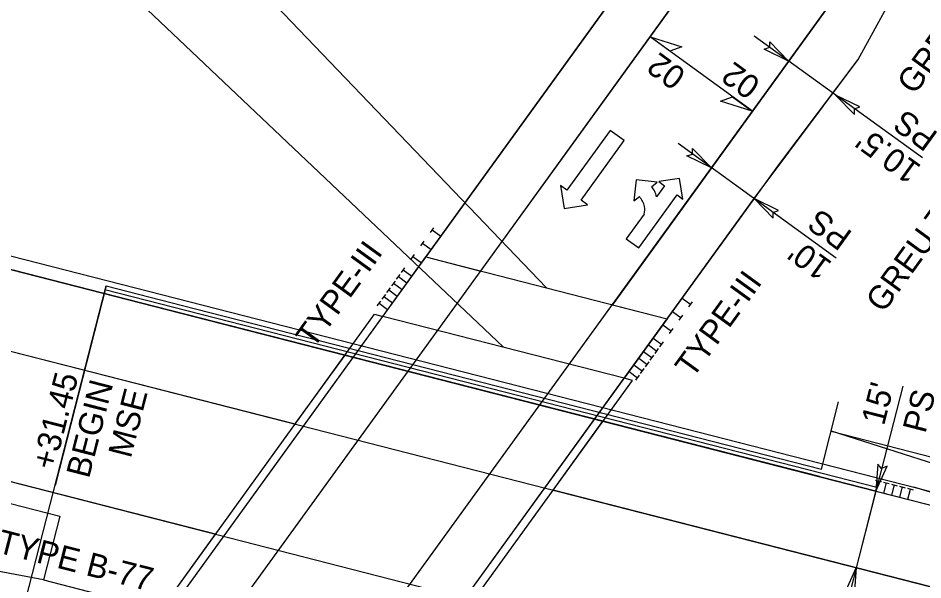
# Model space of a CAD drawing. Extents: x 1183930 to 1185370, y 573068 to 574871.
# Drawn here: x 1184495.2 to 1184666.9, y 574087.2 to 574193.8 of the extents above; entities that cross this region are included whole.
import ezdxf

# ---------------------------------------------------------------- set-up
doc = ezdxf.new("R2010")
doc.units = 0
for name, color, linetype in [('Default', 7, 'Continuous'), ('E_NCDOT_Terrain_Model_Flow_Arrows', 7, 'Continuous'), ('E_NCDOT_Terrain_Model_Spot_Elevation', 7, 'Continuous'), ('E_NCDOT_Vertical_Profile_Ground_Line', 7, 'Continuous'), ('P_NCDOT_Horizontal_Alignment', 7, 'Continuous'), ('P_NCDOT_Horizontal_Alignment_Curve_and_Spiral_Data', 7, 'Continuous'), ('P_NCDOT_Horizontal_Alignment_Direction_Label', 7, 'Continuous'), ('P_NCDOT_Horizontal_Alignment_Station_Label', 7, 'Continuous'), ('P_NCDOT_Horizontal_Alignment_Tick_Large', 7, 'Continuous'), ('P_NCDOT_Horizontal_Alignment_Tick_Small', 7, 'Continuous'), ('P_NCDOT_Vertical_Profile_Grade', 7, 'Continuous'), ('P_SMU_Deck', 7, 'Continuous'), ('PC_BEAM', 7, 'Continuous'), ('PC_COLUMN', 7, 'Continuous'), ('PC_OBJECT', 7, 'Continuous'), ('PC_PADFOOTING', 7, 'Continuous'), ('PC_SLAB', 7, 'Continuous'), ('PS_HATCH', 7, 'Continuous')]:
    doc.layers.add(name, color=color, linetype=linetype)

msp = doc.modelspace()

# ---------------------------------------------------------------- linework, layer by layer
for points in [[(1184637.83, 574189.33), (1184641.42, 574185.65), (1184636.77, 574187.91), (1184637.82, 574188.26)], [(1184654.95, 574176.94), (1184650.33, 574179.2), (1184653.93, 574175.49), (1184653.93, 574176.6)], [(1184623.18, 574169.08), (1184626.77, 574165.41), (1184622.12, 574167.66), (1184623.17, 574168.01)], [(1184639.48, 574157.28), (1184634.87, 574159.55), (1184638.47, 574155.83), (1184638.47, 574156.94)], [(1184658.38, 574109.19), (1184657.97, 574104.07), (1184660.1, 574108.78), (1184659.07, 574108.38)], [(1184652.15, 574084.85), (1184654.25, 574089.54), (1184653.86, 574084.38), (1184653.15, 574085.23)]]:
    msp.add_lwpolyline(points, close=True)
at = {"layer": 'Default'}
for p, q in [((1184433.21, 574164.19), (1184675.4, 574102.19)), ((1184526.4, 574139.3), (1184647.65, 574108.26))]:
    msp.add_line(p, q, dxfattribs=at)
at = {"layer": 'E_NCDOT_Terrain_Model_Flow_Arrows'}
msp.add_line((1184511.87, 574143.02), (1184526.4, 574139.3), dxfattribs=at)
at = {"layer": 'E_NCDOT_Terrain_Model_Spot_Elevation'}
msp.add_line((1184511.65, 574142.3), (1184658.16, 574104.8), dxfattribs=at)
at = {"layer": 'E_NCDOT_Vertical_Profile_Ground_Line'}
for p, q in [((1184449.47, 573978.44), (1184665.23, 574276.54)), ((1184449.47, 573978.44), (1184665.23, 574276.54)), ((1184654.62, 574185.97), (1184679.82, 574231.89)), ((1184654.62, 574185.97), (1184679.82, 574231.89)), ((1184136.14, 574193.27), (1184503.1, 574099.33)), ((1184136.14, 574193.27), (1184503.1, 574099.33)), ((1184136.14, 574193.27), (1184503.1, 574099.33)), ((1184639.53, 574165.99), (1184654.62, 574185.97)), ((1184639.53, 574165.99), (1184654.62, 574185.97)), ((1184413.69, 573853.97), (1184639.53, 574165.99)), ((1184413.69, 573853.97), (1184639.53, 574165.99)), ((1184487.27, 574147.77), (1184526.03, 574137.85)), ((1184515.9, 574140.44), (1184669.44, 574101.14)), ((1184526.03, 574137.85), (1184657.97, 574104.07)), ((1184503.1, 574099.33), (1184500, 574087.22)), ((1184503.1, 574099.33), (1184500, 574087.22)), ((1184500, 574087.22), (1184592.76, 574063.47)), ((1184500, 574087.22), (1184592.76, 574063.47))]:
    msp.add_line(p, q, dxfattribs=at)
at = {"layer": 'P_NCDOT_Horizontal_Alignment'}
for p, q in [((1184397.22, 573889.19), (1184673.34, 574270.68)), ((1184405.59, 573859.83), (1184695.92, 574260.95)), ((1184143.08, 574220.4), (1184971.37, 574008.35)), ((1184143.08, 574220.4), (1184977.73, 574006.73)), ((1184137.13, 574197.15), (1184965.42, 573985.1)), ((1184137.13, 574197.15), (1184971.78, 573983.48)), ((1184647.65, 574108.26), (1184650.88, 574121)), ((1184649.47, 574115.43), (1184671.64, 574109.76)), ((1184649.48, 574115.48), (1185048.75, 573988.56)), ((1184647.89, 574109.23), (1185053.08, 574005.5)), ((1185048.75, 573988.56), (1184665.2, 574104.8))]:
    msp.add_line(p, q, dxfattribs=at)
at = {"layer": 'P_NCDOT_Horizontal_Alignment_Curve_and_Spiral_Data'}
for p, q in [((1184515.9, 574140.44), (1184511.49, 574141.57)), ((1184657.97, 574104.07), (1184515.9, 574140.44)), ((1184647.27, 574106.81), (1184526.03, 574137.85))]:
    msp.add_line(p, q, dxfattribs=at)
at = {"layer": 'P_NCDOT_Horizontal_Alignment_Direction_Label'}
for p, q in [((1184477.22, 574019.34), (1184562.83, 574137.61)), ((1184478.79, 574018.94), (1184564.39, 574137.21)), ((1184562.83, 574137.61), (1184564.39, 574137.21)), ((1184524.61, 574007.21), (1184610.21, 574125.48)), ((1184526.17, 574006.81), (1184611.78, 574125.08)), ((1184611.78, 574125.08), (1184610.21, 574125.48))]:
    msp.add_line(p, q, dxfattribs=at)
at = {"layer": 'P_NCDOT_Horizontal_Alignment_Station_Label'}
for p, q in [((1184564.39, 574137.21), (1184572.62, 574148.59)), ((1184564.39, 574137.21), (1184572.55, 574148.49)), ((1184610.21, 574125.48), (1184564.39, 574137.21)), ((1184610.21, 574125.48), (1184618.52, 574136.95)), ((1184610.21, 574125.48), (1184618.38, 574136.76))]:
    msp.add_line(p, q, dxfattribs=at)
msp.add_lwpolyline([(1184610.21, 574125.48), (1184564.39, 574137.21), (1184572.55, 574148.49), (1184618.38, 574136.76)], close=True, dxfattribs=at)
at = {"layer": 'P_NCDOT_Horizontal_Alignment_Tick_Large'}
for p, q in [((1184575.38, 574152.4), (1184665.23, 574276.54)), ((1184621.21, 574140.67), (1184639.53, 574165.99)), ((1184500, 574087.22), (1184466.75, 574093.41))]:
    msp.add_line(p, q, dxfattribs=at)
at = {"layer": 'P_NCDOT_Horizontal_Alignment_Tick_Small'}
msp.add_line((1184639.53, 574165.99), (1184654.62, 574185.93), dxfattribs=at)
at = {"layer": 'P_NCDOT_Vertical_Profile_Grade'}
for p, q in [((1184573.43, 574153.11), (1184574.1, 574154.04)), ((1184575.38, 574152.4), (1184573.76, 574153.58)), ((1184564.39, 574137.21), (1184575.38, 574152.4)), ((1184571.6, 574150.58), (1184572.27, 574151.51)), ((1184573.55, 574149.87), (1184571.93, 574151.04)), ((1184569.76, 574148.05), (1184570.43, 574148.98)), ((1184571.72, 574147.34), (1184570.1, 574148.51)), ((1184567.93, 574145.52), (1184568.6, 574146.44)), ((1184569.89, 574144.81), (1184568.27, 574145.98)), ((1184566.1, 574142.99), (1184566.77, 574143.91)), ((1184567.01, 574144.25), (1184567.69, 574145.18)), ((1184568.97, 574143.54), (1184567.35, 574144.72)), ((1184565.18, 574141.72), (1184565.85, 574142.65)), ((1184567.14, 574141.01), (1184565.52, 574142.18)), ((1184568.05, 574142.28), (1184566.43, 574143.45)), ((1184564.27, 574140.45), (1184564.94, 574141.38)), ((1184566.22, 574139.75), (1184564.6, 574140.92)), ((1184610.21, 574125.48), (1184621.21, 574140.67)), ((1184621.21, 574140.67), (1184622.83, 574139.5)), ((1184563.35, 574139.19), (1184564.02, 574140.12)), ((1184565.31, 574138.48), (1184563.69, 574139.65)), ((1184622.49, 574139.03), (1184623.16, 574139.96)), ((1184619.38, 574138.14), (1184621, 574136.97)), ((1184620.66, 574136.5), (1184621.33, 574137.43)), ((1184617.54, 574135.61), (1184619.16, 574134.44)), ((1184618.83, 574133.97), (1184619.5, 574134.9)), ((1184615.71, 574133.08), (1184617.33, 574131.9)), ((1184617, 574131.44), (1184617.67, 574132.37)), ((1184613.88, 574130.55), (1184615.5, 574129.37)), ((1184614.8, 574131.81), (1184616.42, 574130.64)), ((1184616.08, 574130.17), (1184616.75, 574131.1)), ((1184612.96, 574129.28), (1184614.58, 574128.11)), ((1184614.25, 574127.64), (1184614.92, 574128.57)), ((1184615.16, 574128.91), (1184615.84, 574129.84)), ((1184611.13, 574126.75), (1184612.75, 574125.58)), ((1184612.05, 574128.01), (1184613.67, 574126.84)), ((1184613.33, 574126.38), (1184614, 574127.31)), ((1184612.42, 574125.11), (1184613.09, 574126.04)), ((1184657.91, 574106.15), (1184659.02, 574105.87)), ((1184657.97, 574104.07), (1184658.47, 574106.01)), ((1184659.42, 574105.76), (1184660.53, 574105.48)), ((1184659.48, 574103.68), (1184659.98, 574105.62)), ((1184660.94, 574105.37), (1184662.05, 574105.09)), ((1184661, 574103.3), (1184661.49, 574105.23)), ((1184662.45, 574104.99), (1184663.56, 574104.7)), ((1184662.51, 574102.91), (1184663.01, 574104.85)), ((1184663.97, 574104.6), (1184665.08, 574104.32)), ((1184664.02, 574102.52), (1184664.52, 574104.46)), ((1184657.97, 574104.07), (1184680.13, 574098.4))]:
    msp.add_line(p, q, dxfattribs=at)
at = {"layer": 'P_SMU_Deck'}
msp.add_line((1184487.54, 574047.99), (1184511.87, 574143.02), dxfattribs=at)
at = {"layer": 'PC_BEAM'}
for p, q in [((1184607.56, 574172.51), (1184599.34, 574161.18)), ((1184610.23, 574170.57), (1184607.56, 574172.51)), ((1184602.01, 574159.24), (1184610.23, 574170.57)), ((1184612.49, 574163.1), (1184612.06, 574159.13)), ((1184616.46, 574162.67), (1184612.49, 574163.1)), ((1184620.69, 574163.38), (1184616.76, 574162.78)), ((1184616.76, 574162.78), (1184617.85, 574161.99)), ((1184621.35, 574159.46), (1184620.69, 574163.38)), ((1184599.34, 574161.18), (1184598.13, 574162.06)), ((1184598.13, 574162.06), (1184598.79, 574157.69)), ((1184615.4, 574161.82), (1184616.46, 574162.67)), ((1184617.85, 574161.99), (1184616.35, 574159.91)), ((1184612.06, 574159.13), (1184613.09, 574159.94)), ((1184612.98, 574150.19), (1184620.26, 574160.25)), ((1184620.26, 574160.25), (1184621.35, 574159.46)), ((1184598.79, 574157.69), (1184603.23, 574158.36)), ((1184603.23, 574158.36), (1184602.01, 574159.24)), ((1184613.97, 574156.63), (1184610.57, 574151.93)), ((1184610.57, 574151.93), (1184612.98, 574150.19))]:
    msp.add_line(p, q, dxfattribs=at)
for centre, radius, start, end in [((1184612.45, 574159.12), 3.99, 11.6336, 42.5122), ((1184610.14, 574157.25), 3.99, 11.5398, 42.3934), ((1184611.86, 574157.46), 2.27, 338.7179, 15.0299)]:
    msp.add_arc(centre, radius, start, end, dxfattribs=at)
at = {"layer": 'PC_COLUMN'}
for points in [[(1184615.11, 574190.24), (1184621.14, 574188.33), (1184618.85, 574187.52)], [(1184634.49, 574176.15), (1184628.46, 574178.06), (1184630.75, 574178.87)]]:
    msp.add_lwpolyline(points, close=True, dxfattribs=at)
at = {"layer": 'PC_OBJECT'}
for p, q in [((1184665.23, 574276.54), (1184572.55, 574148.49)), ((1184583.05, 574145.94), (1184673.34, 574270.68)), ((1184695.92, 574260.95), (1184608.09, 574139.6)), ((1184654.62, 574185.97), (1184679.82, 574231.89)), ((1184143.08, 574220.4), (1184547.76, 574116.8)), ((1184136.14, 574193.27), (1184503.1, 574099.33)), ((1184634.87, 574159.55), (1184654.62, 574185.97)), ((1184639.53, 574165.99), (1184654.6, 574185.95)), ((1184610.21, 574125.48), (1184639.53, 574165.99)), ((1184618.52, 574136.95), (1184634.87, 574159.55)), ((1184557.22, 574129.86), (1184515.9, 574140.44)), ((1184547.76, 574116.8), (1184557.22, 574129.86)), ((1184596.71, 574104.27), (1184606.17, 574117.33)), ((1184606.17, 574117.33), (1184657.97, 574104.07)), ((1184977.73, 574006.73), (1184596.71, 574104.27)), ((1184657.97, 574104.07), (1184669.44, 574101.14)), ((1184503.1, 574099.33), (1184500, 574087.22)), ((1184522.23, 574081.53), (1184532.63, 574095.9)), ((1184500, 574087.22), (1184500.97, 574086.97))]:
    msp.add_line(p, q, dxfattribs=at)
for points in [[(1184532.63, 574095.9), (1184476.98, 574110.15), (1184137.13, 574197.15)], [(1184515.9, 574140.44), (1184487.27, 574147.77), (1184290.79, 574186.71)], [(1184572.55, 574148.49), (1184582.97, 574145.82), (1184583.05, 574145.94)], [(1184608.09, 574139.6), (1184607.96, 574139.42), (1184618.38, 574136.76), (1184618.52, 574136.95)]]:
    msp.add_lwpolyline(points, dxfattribs=at)
at = {"layer": 'PC_PADFOOTING'}
for p, q in [((1184666.82, 574167.27), (1184634.9, 574190.38)), ((1184650.42, 574148.29), (1184620.43, 574170)), ((1184511.87, 574143.02), (1184502.17, 574105.16)), ((1184663.07, 574123.98), (1184654.25, 574089.54)), ((1184658, 574104.2), (1184649.3, 574070.22))]:
    msp.add_line(p, q, dxfattribs=at)
at = {"layer": 'PC_SLAB'}
msp.add_line((1184634.53, 574176.13), (1184615.11, 574190.24), dxfattribs=at)
at = {"layer": 'PS_HATCH'}
for p, q in [((1184595.46, 574142.62), (1184427.86, 574317.47)), ((1184587.3, 574131.35), (1184440.16, 574270.82))]:
    msp.add_line(p, q, dxfattribs=at)

# ---------------------------------------------------------------- texts
at = {"layer": 'PC_PADFOOTING'}
for s, rotation, p in [('PS', 144.103, (1184670.01, 574171.92)), ("10.5'", 144.103, (1184666.82, 574165.69)), ('PS', 144.103, (1184653.74, 574153.08)), ("10'", 144.103, (1184649.9, 574147.38)), ('+31.45', 75.6405, (1184502.04, 574107.89)), ('BEGIN', 75.6405, (1184508.61, 574106.31)), (' MSE', 75.6405, (1184516.14, 574108.53)), ("15'", 75.6405, (1184659.51, 574116.34)), ('PS', 75.6405, (1184667.37, 574114.86))]:
    msp.add_text(s, height=4.5, rotation=rotation, dxfattribs=at).set_placement(p)
at = {"layer": 'PC_SLAB'}
for p in [(1184622.2, 574183.56), (1184636.35, 574181.79)]:
    msp.add_text('02', height=4.5, rotation=143.9771, dxfattribs=at).set_placement(p)
at = {"layer": 'PS_HATCH'}
for s, rotation, p in [('GREU TL-2 ', 54.0376, (1184665.32, 574179.08)), ('GREU TL-2 ', 54.0376, (1184659.4, 574137.69)), ('TYPE-III', 54.0376, (1184551.2, 574130.94)), ('TYPE-III', 54.0376, (1184623.2, 574125.3)), ('TYPE B-77', 345.6405, (1184490.98, 574092.48))]:
    msp.add_text(s, height=4.5, rotation=rotation, dxfattribs=at).set_placement(p)

doc.saveas('drawing.dxf')
